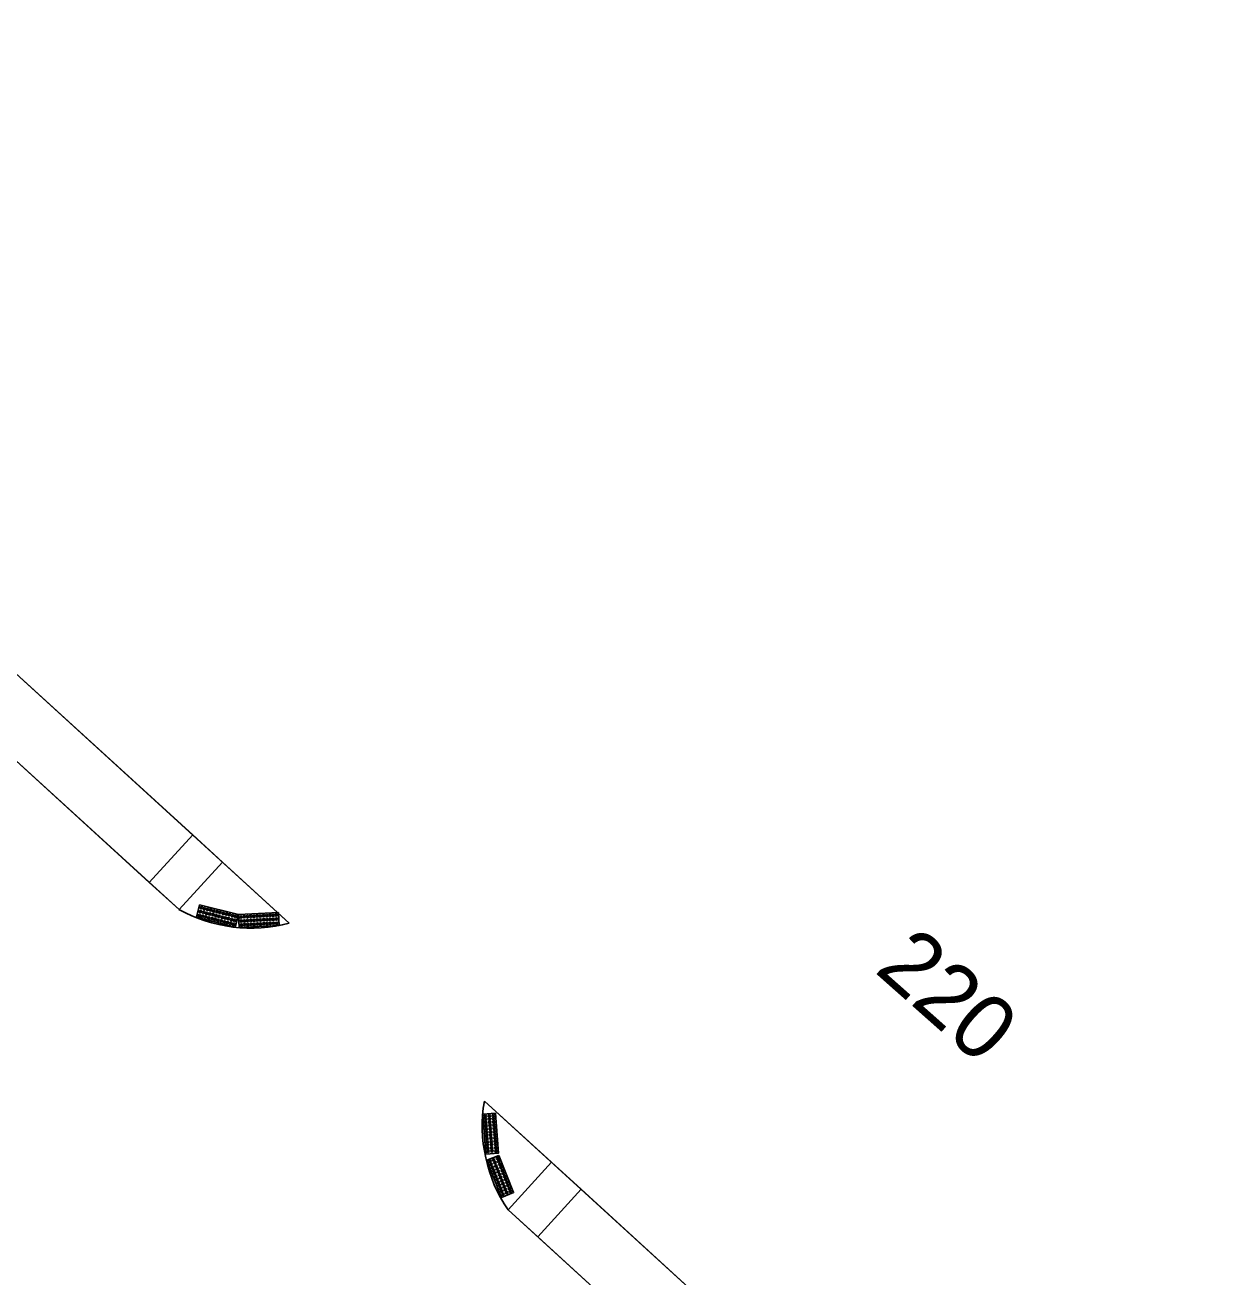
# Model space of a CAD drawing. Extents: x -5665 to 1997148, y 4 to 827579.
# Drawn here: x 1970811.6 to 1970961.6, y 803376.5 to 803532.3 of the extents above; entities that cross this region are included whole.
import ezdxf

# ---------------------------------------------------------------- set-up
doc = ezdxf.new("R2010")
doc.units = 0
doc.layers.add('RD_HC_TX_Rel_Sta50', color=7, linetype='Continuous')
doc.layers.add('RD_PD_SW', color=7, linetype='Continuous')

msp = doc.modelspace()

# ---------------------------------------------------------------- linework, layer by layer
at = {"layer": 'RD_PD_SW'}
for p, q in [((1970844.51, 803420.55), (1970721.97, 803532.35)), ((1970830.78, 803422.25), (1970716.58, 803526.44)), ((1970716.58, 803526.44), (1970827.08, 803425.62)), ((1970832.48, 803431.53), (1970729.48, 803525.5)), ((1970827.08, 803425.62), (1970832.48, 803431.53)), ((1970832.48, 803431.53), (1970827.08, 803425.62)), ((1970827.08, 803425.62), (1970832.48, 803431.53)), ((1970836.17, 803428.16), (1970832.48, 803431.53)), ((1970830.78, 803422.25), (1970836.17, 803428.16)), ((1970836.17, 803428.16), (1970830.78, 803422.25)), ((1970830.78, 803422.25), (1970836.17, 803428.16)), ((1970844.51, 803420.55), (1970836.17, 803428.16)), ((1970827.08, 803425.62), (1970830.78, 803422.25)), ((1970961.62, 803313.72), (1970868.8, 803398.4)), ((1970877.14, 803390.79), (1970868.8, 803398.4)), ((1970871.75, 803384.88), (1970877.14, 803390.79)), ((1970877.14, 803390.79), (1970871.75, 803384.88)), ((1970871.75, 803384.88), (1970877.14, 803390.79)), ((1970880.83, 803387.42), (1970877.14, 803390.79)), ((1970875.44, 803381.51), (1970880.83, 803387.42)), ((1970880.83, 803387.42), (1970875.44, 803381.51)), ((1970875.44, 803381.51), (1970880.83, 803387.42)), ((1970948.78, 803325.43), (1970880.83, 803387.42)), ((1970947.88, 803315.42), (1970871.75, 803384.88)), ((1970871.75, 803384.88), (1970875.44, 803381.51)), ((1970875.44, 803381.51), (1970943.38, 803319.52))]:
    msp.add_line(p, q, dxfattribs=at)
for points in [[(1970838.17, 803421.61), (1970833.34, 803422.83), (1970832.95, 803421.28), (1970837.78, 803420.06)], [(1970843.15, 803421.87), (1970838.17, 803421.61), (1970838.26, 803420.02), (1970843.24, 803420.27)], [(1970870.19, 803396.9), (1970870.57, 803391.93), (1970868.97, 803391.81), (1970868.59, 803396.78)], [(1970870.6, 803391.65), (1970872.43, 803387.01), (1970870.94, 803386.42), (1970869.11, 803391.06)]]:
    msp.add_lwpolyline(points, close=True, dxfattribs=at)
for centre, radius in [((1970833.32, 803421.5), 0.146), ((1970833.32, 803421.5), 0.073), ((1970833.44, 803421.98), 0.146), ((1970833.44, 803421.98), 0.073), ((1970833.56, 803422.47), 0.146), ((1970833.56, 803422.47), 0.073), ((1970833.7, 803421.4), 0.146), ((1970833.7, 803421.4), 0.073), ((1970833.83, 803421.88), 0.146), ((1970833.83, 803421.88), 0.073), ((1970833.95, 803422.37), 0.146), ((1970833.95, 803422.37), 0.073), ((1970834.21, 803421.78), 0.146), ((1970834.21, 803421.78), 0.073), ((1970834.34, 803422.28), 0.146), ((1970834.34, 803422.28), 0.073), ((1970834.6, 803421.69), 0.146), ((1970834.6, 803421.69), 0.073), ((1970834.73, 803422.18), 0.146), ((1970834.73, 803422.18), 0.073), ((1970834.99, 803421.59), 0.146), ((1970834.99, 803421.59), 0.073), ((1970835.11, 803422.08), 0.146), ((1970835.11, 803422.08), 0.073), ((1970835.38, 803421.49), 0.146), ((1970835.38, 803421.49), 0.073), ((1970835.5, 803421.98), 0.146), ((1970835.5, 803421.98), 0.073), ((1970835.77, 803421.39), 0.146), ((1970835.77, 803421.39), 0.073), ((1970835.89, 803421.88), 0.146), ((1970835.89, 803421.88), 0.073), ((1970836.28, 803421.79), 0.146), ((1970836.28, 803421.79), 0.073), ((1970836.67, 803421.69), 0.146), ((1970836.67, 803421.69), 0.073), ((1970837.05, 803421.59), 0.146), ((1970837.05, 803421.59), 0.073), ((1970837.44, 803421.49), 0.146), ((1970837.44, 803421.49), 0.073), ((1970837.83, 803421.39), 0.146), ((1970837.83, 803421.39), 0.073), ((1970838.49, 803421.33), 0.146), ((1970838.89, 803421.35), 0.146), ((1970839.29, 803421.37), 0.146), ((1970839.69, 803421.39), 0.146), ((1970839.69, 803421.39), 0.073), ((1970840.09, 803421.42), 0.146), ((1970840.09, 803421.42), 0.073), ((1970840.49, 803421.44), 0.146), ((1970840.49, 803421.44), 0.073), ((1970840.89, 803421.46), 0.146), ((1970840.89, 803421.46), 0.073), ((1970841.29, 803421.48), 0.146), ((1970841.29, 803421.48), 0.073), ((1970841.69, 803421.5), 0.146), ((1970841.69, 803421.5), 0.073), ((1970842.09, 803421.52), 0.146), ((1970842.09, 803421.52), 0.073), ((1970842.49, 803421.54), 0.146), ((1970842.49, 803421.54), 0.073), ((1970842.89, 803421.56), 0.146), ((1970842.89, 803421.56), 0.073), ((1970834.09, 803421.3), 0.146), ((1970834.09, 803421.3), 0.073), ((1970834.48, 803421.2), 0.146), ((1970834.48, 803421.2), 0.073), ((1970834.87, 803421.1), 0.146), ((1970834.87, 803421.1), 0.073), ((1970835.26, 803421.01), 0.146), ((1970835.26, 803421.01), 0.073), ((1970835.64, 803420.91), 0.146), ((1970835.64, 803420.91), 0.073), ((1970836.03, 803420.81), 0.146), ((1970836.03, 803420.81), 0.073), ((1970836.15, 803421.29), 0.146), ((1970836.15, 803421.29), 0.073), ((1970836.42, 803420.71), 0.146), ((1970836.42, 803420.71), 0.073), ((1970836.54, 803421.2), 0.146), ((1970836.54, 803421.2), 0.073), ((1970836.81, 803420.61), 0.146), ((1970836.81, 803420.61), 0.073), ((1970836.93, 803421.1), 0.146), ((1970836.93, 803421.1), 0.073), ((1970837.19, 803420.52), 0.146), ((1970837.19, 803420.52), 0.073), ((1970837.32, 803421), 0.146), ((1970837.32, 803421), 0.073), ((1970837.58, 803420.42), 0.146), ((1970837.58, 803420.42), 0.073), ((1970837.7, 803420.9), 0.146), ((1970837.7, 803420.9), 0.073), ((1970838.52, 803420.82), 0.146), ((1970838.55, 803420.33), 0.146), ((1970838.49, 803421.33), 0.073), ((1970838.52, 803420.82), 0.073), ((1970838.55, 803420.33), 0.073), ((1970838.92, 803420.84), 0.146), ((1970838.94, 803420.35), 0.146), ((1970838.89, 803421.35), 0.073), ((1970838.92, 803420.84), 0.073), ((1970838.94, 803420.35), 0.073), ((1970839.32, 803420.87), 0.146), ((1970839.34, 803420.37), 0.146), ((1970839.29, 803421.37), 0.073), ((1970839.32, 803420.87), 0.073), ((1970839.34, 803420.37), 0.073), ((1970839.72, 803420.89), 0.146), ((1970839.74, 803420.39), 0.146), ((1970839.72, 803420.89), 0.073), ((1970839.74, 803420.39), 0.073), ((1970840.12, 803420.91), 0.146), ((1970840.14, 803420.41), 0.146), ((1970840.12, 803420.91), 0.073), ((1970840.14, 803420.41), 0.073), ((1970840.52, 803420.93), 0.146), ((1970840.54, 803420.43), 0.146), ((1970840.52, 803420.93), 0.073), ((1970840.54, 803420.43), 0.073), ((1970840.92, 803420.95), 0.146), ((1970840.94, 803420.45), 0.146), ((1970840.92, 803420.95), 0.073), ((1970840.94, 803420.45), 0.073), ((1970841.32, 803420.97), 0.146), ((1970841.34, 803420.47), 0.146), ((1970841.32, 803420.97), 0.073), ((1970841.34, 803420.47), 0.073), ((1970841.72, 803420.99), 0.146), ((1970841.74, 803420.49), 0.146), ((1970841.72, 803420.99), 0.073), ((1970841.74, 803420.49), 0.073), ((1970842.11, 803421.01), 0.146), ((1970842.14, 803420.51), 0.146), ((1970842.11, 803421.01), 0.073), ((1970842.14, 803420.51), 0.073), ((1970842.51, 803421.03), 0.146), ((1970842.54, 803420.53), 0.146), ((1970842.51, 803421.03), 0.073), ((1970842.54, 803420.53), 0.073), ((1970842.91, 803421.05), 0.146), ((1970842.94, 803420.55), 0.146), ((1970842.91, 803421.05), 0.073), ((1970842.94, 803420.55), 0.073), ((1970868.91, 803396.52), 0.146), ((1970868.91, 803396.52), 0.073), ((1970869.41, 803396.56), 0.146), ((1970869.41, 803396.56), 0.073), ((1970869.91, 803396.6), 0.146), ((1970869.91, 803396.6), 0.073), ((1970868.94, 803396.13), 0.146), ((1970868.97, 803395.73), 0.146), ((1970869, 803395.33), 0.146), ((1970868.94, 803396.13), 0.073), ((1970869.03, 803394.93), 0.146), ((1970868.97, 803395.73), 0.073), ((1970869, 803395.33), 0.073), ((1970869.03, 803394.93), 0.073), ((1970869.44, 803396.16), 0.146), ((1970869.47, 803395.76), 0.146), ((1970869.5, 803395.37), 0.146), ((1970869.44, 803396.16), 0.073), ((1970869.53, 803394.97), 0.146), ((1970869.47, 803395.76), 0.073), ((1970869.5, 803395.37), 0.073), ((1970869.53, 803394.97), 0.073), ((1970869.94, 803396.2), 0.146), ((1970869.97, 803395.8), 0.146), ((1970870.01, 803395.4), 0.146), ((1970869.94, 803396.2), 0.073), ((1970870.04, 803395.01), 0.146), ((1970869.97, 803395.8), 0.073), ((1970870.01, 803395.4), 0.073), ((1970870.04, 803395.01), 0.073), ((1970869.06, 803394.53), 0.146), ((1970869.09, 803394.13), 0.146), ((1970869.12, 803393.73), 0.146), ((1970869.06, 803394.53), 0.073), ((1970869.15, 803393.33), 0.146), ((1970869.09, 803394.13), 0.073), ((1970869.12, 803393.73), 0.073), ((1970869.56, 803394.57), 0.146), ((1970869.59, 803394.17), 0.146), ((1970869.62, 803393.77), 0.146), ((1970869.56, 803394.57), 0.073), ((1970869.65, 803393.37), 0.146), ((1970869.59, 803394.17), 0.073), ((1970869.62, 803393.77), 0.073), ((1970869.65, 803393.37), 0.073), ((1970870.07, 803394.61), 0.146), ((1970870.1, 803394.21), 0.146), ((1970870.13, 803393.81), 0.146), ((1970870.07, 803394.61), 0.073), ((1970870.16, 803393.41), 0.146), ((1970870.1, 803394.21), 0.073), ((1970870.13, 803393.81), 0.073), ((1970870.16, 803393.41), 0.073), ((1970869.18, 803392.93), 0.146), ((1970869.21, 803392.54), 0.146), ((1970869.15, 803393.33), 0.073), ((1970869.25, 803392.14), 0.146), ((1970869.18, 803392.93), 0.073), ((1970869.21, 803392.54), 0.073), ((1970869.25, 803392.14), 0.073), ((1970869.68, 803392.97), 0.146), ((1970869.71, 803392.57), 0.146), ((1970869.74, 803392.18), 0.146), ((1970869.68, 803392.97), 0.073), ((1970869.71, 803392.57), 0.073), ((1970869.74, 803392.18), 0.073), ((1970870.19, 803393.01), 0.146), ((1970870.22, 803392.61), 0.146), ((1970870.25, 803392.21), 0.146), ((1970870.19, 803393.01), 0.073), ((1970870.22, 803392.61), 0.073), ((1970870.25, 803392.21), 0.073), ((1970869.49, 803390.9), 0.146), ((1970869.49, 803390.9), 0.073), ((1970869.63, 803390.53), 0.146), ((1970869.63, 803390.53), 0.073), ((1970869.78, 803390.16), 0.146), ((1970869.95, 803391.09), 0.146), ((1970869.95, 803391.09), 0.073), ((1970870.1, 803390.72), 0.146), ((1970870.1, 803390.72), 0.073), ((1970870.25, 803390.34), 0.146), ((1970870.25, 803390.34), 0.073), ((1970870.43, 803391.27), 0.146), ((1970870.43, 803391.27), 0.073), ((1970870.57, 803390.9), 0.146), ((1970870.57, 803390.9), 0.073), ((1970870.72, 803390.53), 0.146), ((1970870.72, 803390.53), 0.073), ((1970870.87, 803390.16), 0.146), ((1970869.78, 803390.16), 0.073), ((1970869.93, 803389.79), 0.146), ((1970869.93, 803389.79), 0.073), ((1970870.08, 803389.42), 0.146), ((1970870.08, 803389.42), 0.073), ((1970870.22, 803389.04), 0.146), ((1970870.22, 803389.04), 0.073), ((1970870.37, 803388.67), 0.146), ((1970870.39, 803389.97), 0.146), ((1970870.37, 803388.67), 0.073), ((1970870.39, 803389.97), 0.073), ((1970870.54, 803389.6), 0.146), ((1970870.54, 803389.6), 0.073), ((1970870.69, 803389.23), 0.146), ((1970870.69, 803389.23), 0.073), ((1970870.83, 803388.86), 0.146), ((1970870.83, 803388.86), 0.073), ((1970870.87, 803390.16), 0.073), ((1970871.01, 803389.79), 0.146), ((1970871.01, 803389.79), 0.073), ((1970871.16, 803389.41), 0.146), ((1970871.16, 803389.41), 0.073), ((1970871.31, 803389.04), 0.146), ((1970871.31, 803389.04), 0.073), ((1970871.45, 803388.67), 0.146), ((1970871.45, 803388.67), 0.073), ((1970870.52, 803388.3), 0.146), ((1970870.52, 803388.3), 0.073), ((1970870.66, 803387.93), 0.146), ((1970870.66, 803387.93), 0.073), ((1970870.81, 803387.56), 0.146), ((1970870.81, 803387.56), 0.073), ((1970870.96, 803387.18), 0.146), ((1970870.98, 803388.48), 0.146), ((1970870.96, 803387.18), 0.073), ((1970870.98, 803388.48), 0.073), ((1970871.13, 803388.11), 0.146), ((1970871.13, 803388.11), 0.073), ((1970871.27, 803387.74), 0.146), ((1970871.27, 803387.74), 0.073), ((1970871.42, 803387.37), 0.146), ((1970871.42, 803387.37), 0.073), ((1970871.6, 803388.3), 0.146), ((1970871.6, 803388.3), 0.073), ((1970871.75, 803387.93), 0.146), ((1970871.75, 803387.93), 0.073), ((1970871.89, 803387.55), 0.146), ((1970871.89, 803387.55), 0.073), ((1970872.04, 803387.18), 0.146), ((1970872.04, 803387.18), 0.073), ((1970871.1, 803386.81), 0.146), ((1970871.1, 803386.81), 0.073), ((1970871.57, 803386.99), 0.146), ((1970871.57, 803386.99), 0.073)]:
    msp.add_circle(centre, radius, dxfattribs=at)
for centre, start, end in [((1970839.75, 803438.43), 240.9764, 284.9048), ((1970887.03, 803395.3), 170.3457, 214.2741)]:
    msp.add_arc(centre, 18.5, start, end, dxfattribs=at)

# ---------------------------------------------------------------- texts
at = {"layer": 'RD_HC_TX_Rel_Sta50'}
msp.add_text('220', height=8, rotation=318.4058, dxfattribs=at).set_placement((1970917.21, 803414.57))

doc.saveas('drawing.dxf')
